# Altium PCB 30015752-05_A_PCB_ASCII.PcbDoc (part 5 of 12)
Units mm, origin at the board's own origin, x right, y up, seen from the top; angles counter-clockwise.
Board outline 100.05 x 72 mm, 10 copper layers (Top, GND_2, Signal_3, Signal_4, PWR_5, GND_6, Signal_7, Signal_8, GND_9, Bottom), stack 1.493 mm thick; 577 components, 546 nets, 2389 pads, 1412 vias.
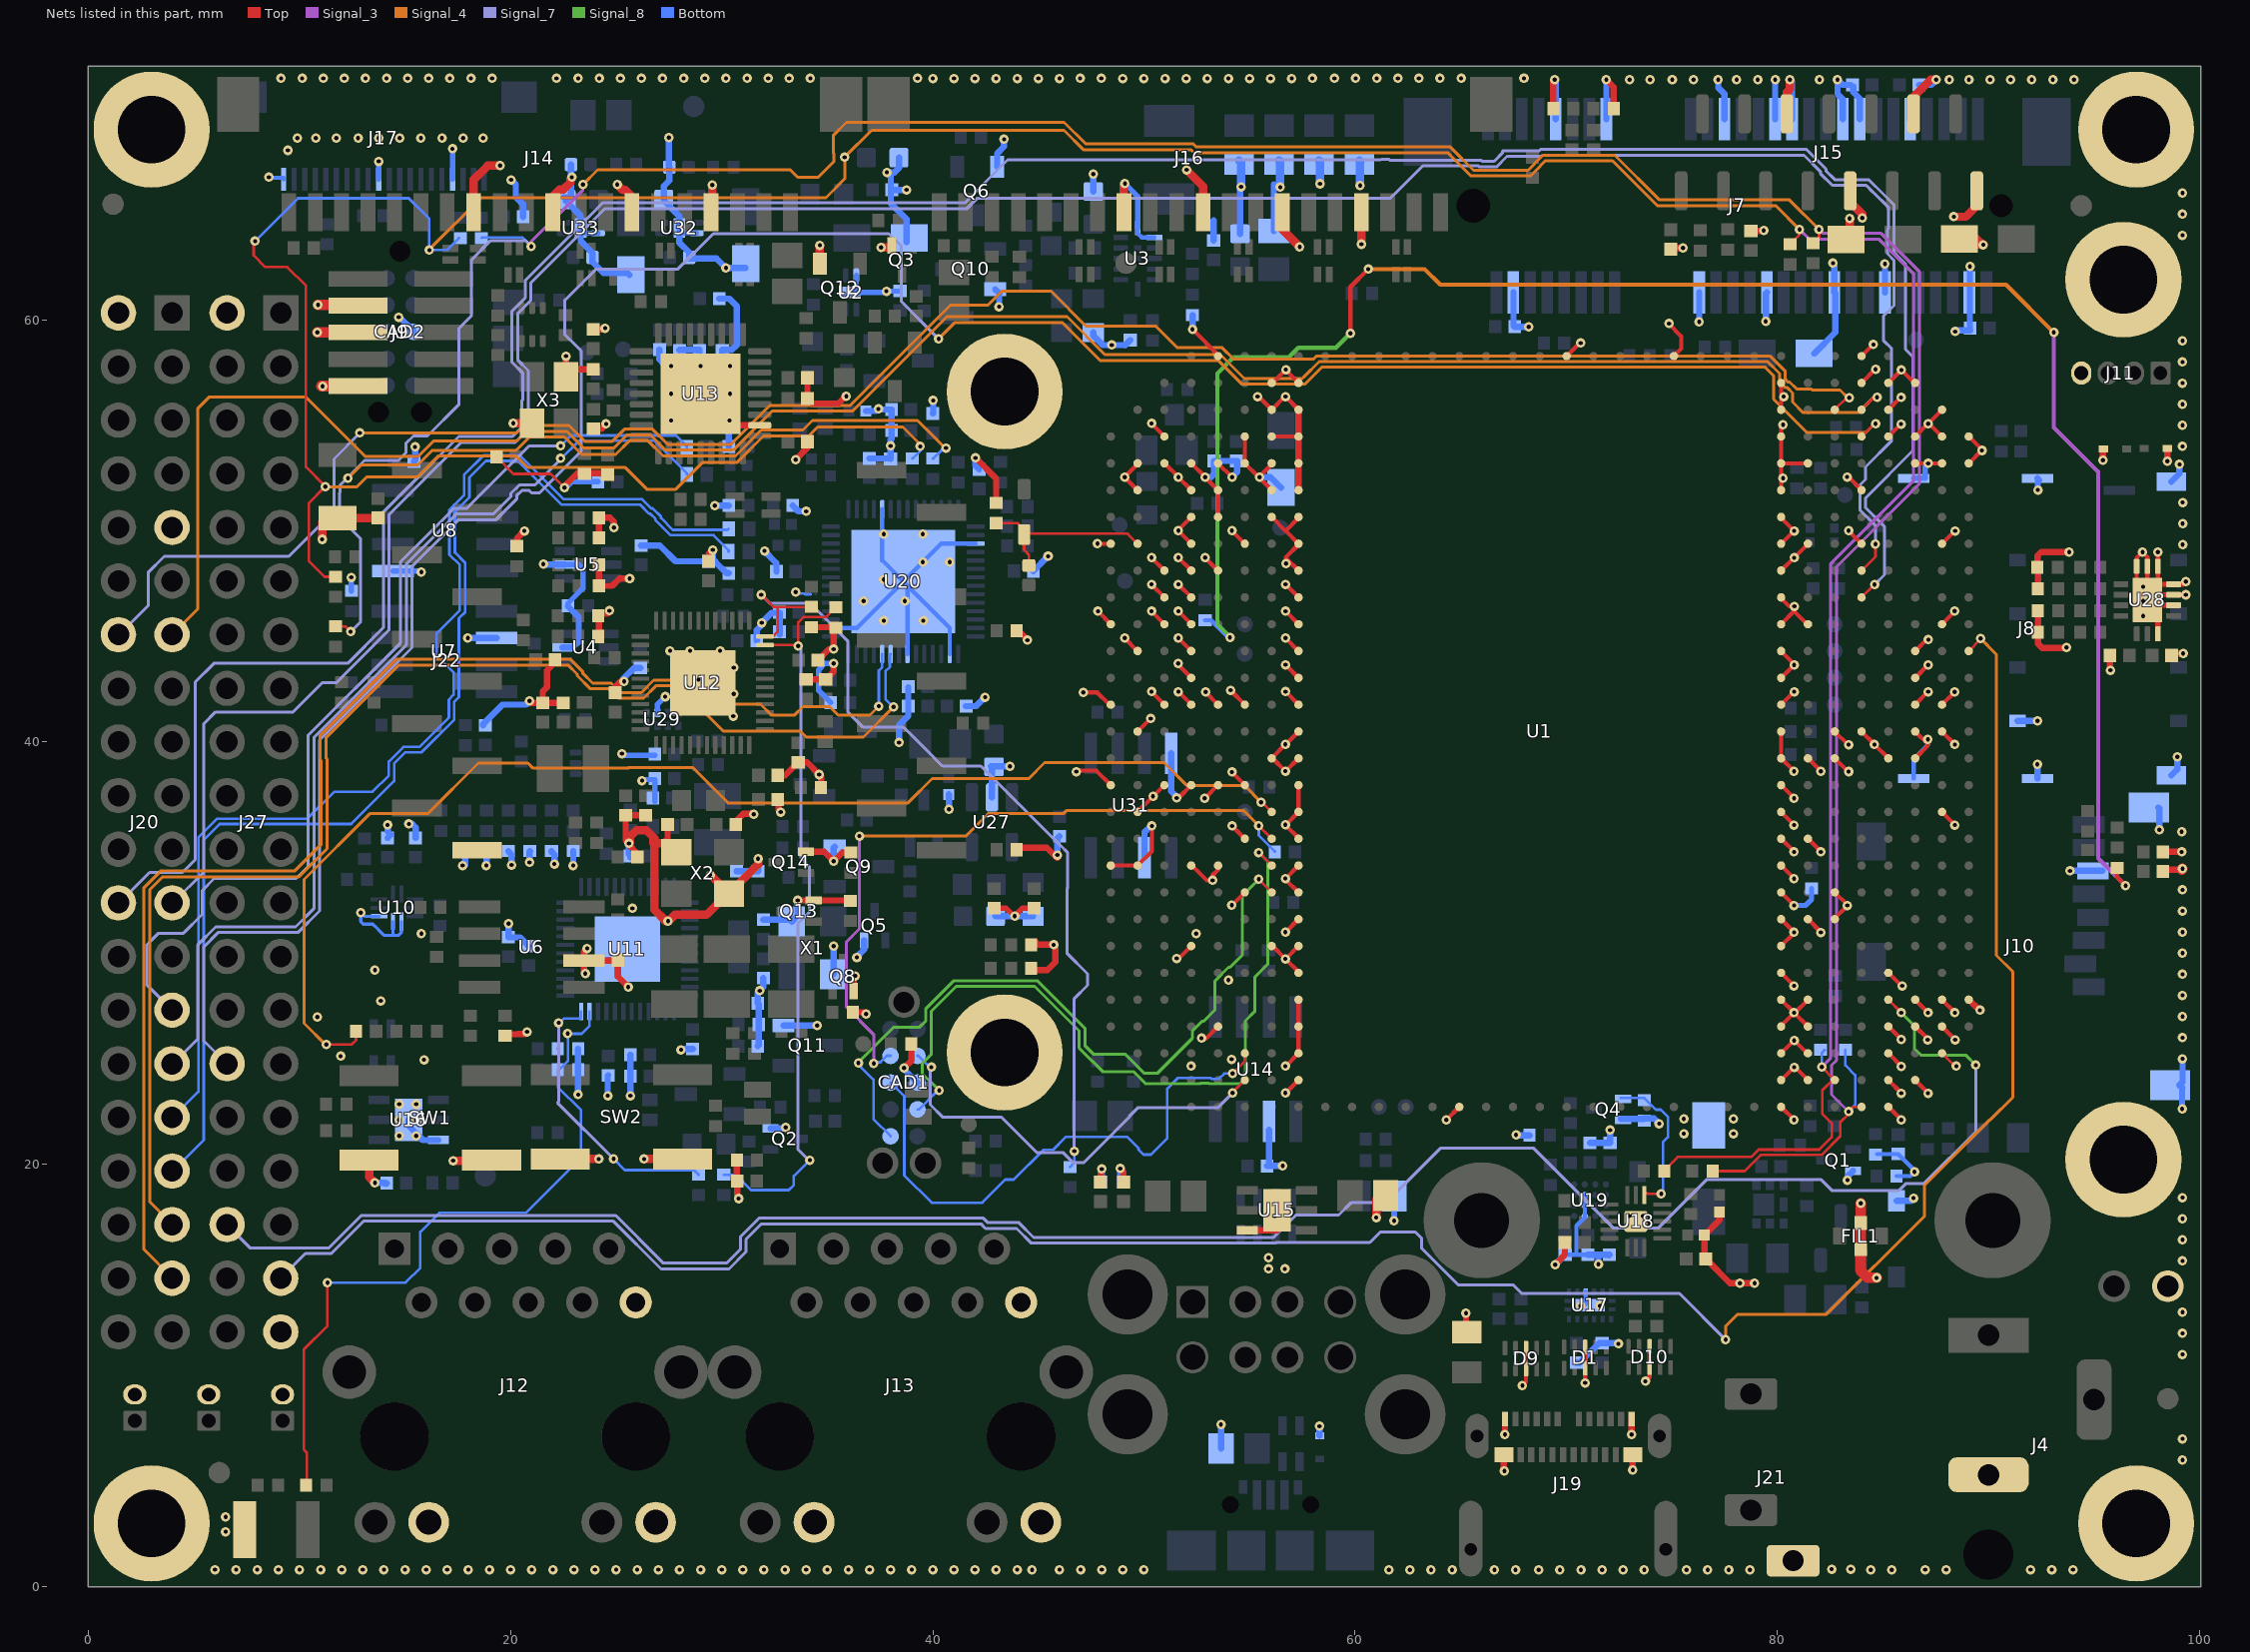
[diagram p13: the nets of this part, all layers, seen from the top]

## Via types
v1: diameter 0.45, hole 0.2, Top to Bottom, tented both sides, 1412 vias

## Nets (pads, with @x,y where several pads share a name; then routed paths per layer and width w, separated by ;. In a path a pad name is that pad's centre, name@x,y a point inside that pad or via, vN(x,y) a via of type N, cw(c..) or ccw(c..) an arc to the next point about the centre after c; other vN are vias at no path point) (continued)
GND: C1.2 C2.1 C3.1 C4.1 C5.1 C6.1 C7.2 C8.1 C9.1 C10.1 C11.1 C12.1 C15.1 C16.1 C17.1 C18.1 C19.2 C20.2 C21.2 C22.1 C23.1 C24.1 C25.1 C26.1 C27.1 C28.1 C29.2 C30.2 C31.1 C32.1 C33.1 C37.1 C38.1 C39.1 C40.1 C42.1 C43.1 C44.1 C45.1 C46.2 C47.1 C48.1 C49.1 C50.1 C51.1 C52.1 C53.1 C54.1 C55.1 C56.1 C57.1 C58.1 C59.1 C60.1 C61.1 C62.1 C63.1 C64.2 C65.1 C66.1 C67.1 C68.1 C69.1 C70.1 C71.1 C72.1 C73.1 C74.1 C75.1 C76.1 C77.1 C78.1 C80.1 C81.2 C82.2 C83.1 C84.2 C85.1 C86.1 C87.1 C88.1 C90.1 C91.1 C92.1 C93.1 C94.1 C95.1 C96.1 C97.1 C98.1 C99.1 C100.1 C101.1 C102.1 C103.1 C104.1 C105.1 C106.1 C107.1 C108.1 C109.2 C112.2 C113.2 C114.2 C115.2 C116.2 C117.2 C118.2 C119.2 C120.1 C121.2 C122.2 C123.2 C124.1 C125.2 C126.2 C128.1 C129.1 C130.2 C131.1 C132.1 C135.1 C136.1 C143.1 C145.1 C146.1 C147.1 C148.1 C149.1 C154.1 C155.2 C156.1 C157.1 C158.1 C159.2 C160.1 C161.1 CAD1.3 CAD2.3 D1.3 D1.8 D2.1 D3.A D6.1 D7.1 D9.3 D9.8 D10.3 D10.8 D14.A FIL1.2 J2.2 J3.2 J4.2 J5.2 J6.2 J7.4 J7.9 J7.15 J7.18 J7.21 J7.26 J7.27 J7.29 J7.34 J7.35 J7.37 J7.40 J7.43 J7.50 J8.5 J8.11 J8.12 J8.13 J8.14 J8.15 J8.16 J9.3 J9.5 J9.9 J10.6 J10.11 J10.12 J11.4 J12.10 J12.D2 J12.D4 J13.10 J13.D2 J13.D4 J14.4 J14.7 J14.10 J14.13 J15.6 J15.9 J15.12 J15.15 J16.4 J16.7 J16.10 J16.13 J17.1 J17.10 J17.17 J19.A1 J19.A12 J19.B1 J19.B12 J20.2 J20.9 J21.1 J22.10 J27.2 J27.39 L13.1 L14.1 L39.1 NT1.2 pad.0@43.4,25.3 pad.0@43.4,56.6 pad.0@96.4,20.225 pad.0@96.4,61.9 pad.TOOL1 pad.TOOL2 pad.TOOL3 pad.TOOL4 Q1.S Q2.S Q3.S Q4.S Q5.S Q6.S Q8.S Q9.S Q10.S Q11.S Q12.S Q13.S Q14.S R12.1 R24.1 R25.1 R27.1 R30.2 R33.1 R34.2 R37.1 R39.1 R44.1 R50.1 R59.1 R61.1 R82.1 R85.1 R87.1 R89.1 R91.1 R93.1 R95.1 R97.1 R99.1 R101.1 R108.2 R109.2 R112.1 R114.1 R117.2 R119.1 R121.1 R123.1 R125.1 R127.1 R129.1 R131.1 R133.1 R138.1 R139.1 R140.1 R141.1 R150.1 R153.1 R163.2 R189.1 R195.1 R197.2 R198.1 R214.2 R216.2 R217.1 R218.1 R258.1 SW1.1 SW1.2 SW2.1 SW2.2 U1.A4 U1.A5 U1.A25 U1.AF2 U1.AF3 U1.AF4 U1.AF5 U1.AF6 U1.AF7 U1.AF8 U1.AF9 U1.AF10 U1.AF11 U1.AF12 U1.AF13 U1.AF14 U1.AF15 U1.AF16 U1.AF17 U1.AF18 U1.AF19 U1.AF20 U1.AF21 U1.AF22 U1.AF23 U1.AF24 U1.AF25 U1.AF26 U1.AF27 U1.AF28 U1.AG2 U1.AG3 U1.AG4 U1.AG5 U1.AG6 U1.AG7 U1.AG16 U1.AG23 U1.AH4 U1.AH5 U1.AH8 U1.AH14 U1.AH17 U1.AH19 U1.AH21 U1.AJ1 U1.AJ5 U1.AJ6 U1.AJ7 U1.AJ9 U1.AJ14 U1.AJ17 U1.AJ20 U1.AJ26 U1.AK5 U1.AK6 U1.AK7 U1.AK8 U1.AK9 U1.AK10 U1.AK11 U1.AK12 U1.AK13 U1.AK14 U1.AK17 U1.AK20 U1.AK23 U1.AL4 U1.AL5 U1.AL9 U1.AL10 U1.AL11 U1.AL14 U1.AL17 U1.AM5 U1.AM6 U1.AM12 U1.AM15 U1.AM18 U1.AM20 U1.AN8 U1.AN11 U1.AN14 U1.AN17 U1.AN20 U1.B3 U1.B4 U1.B5 U1.B8 U1.B11 U1.B14 U1.B15 U1.B18 U1.B25 U1.B26 U1.B27 U1.C2 U1.C4 U1.C5 U1.C12 U1.C13 U1.C14 U1.C15 U1.C16 U1.C25 U1.C26 U1.C28 U1.D2 U1.D3 U1.D4 U1.D16 U1.D24 U1.D26 U1.D27 U1.D28 U1.D29 U1.E1 U1.E2 U1.E6 U1.E8 U1.E15 U1.F15 U1.F16 U1.F21 U1.F22 U1.G5 U1.G8 U1.G11 U1.G16 U1.G19 U1.G22 U1.G25 U1.G26 U1.G27 U1.G28 U1.H2 U1.H3 U1.H4 U1.H5 U1.H6 U1.H7 U1.H8 U1.H9 U1.H10 U1.H11 U1.H12 U1.H13 U1.H14 U1.H15 U1.H16 U1.H17 U1.H18 U1.H19 U1.H20 U1.H21 U1.H22 U1.H23 U1.H24 U1.H25 U1.H26 U1.H27 U1.H28 U1.H29 U1.M1 U1.T1 U1.Y29 U2.2 U2.5 U3.1 U3.12 U4.2 U5.2 U6.2 U7.2 U8.5 U10.1 U10.2 U10.3 U11.49 U12.49 U13.11 U13.37 U14.6 U15.3 U15.7 U16.3 U16.7 U17.11 U17.17 U18.17 U19.B3 U19.C3 U19.D3 U20.3 U20.16 U20.21 U20.30 U20.47 U20.57 U27.2 U28.2 U28.3 U28.4 U28.5 U28.6 U28.7 U28.14 U28.15 U29.2 U31.4 U31.6 U32.2 U32.5 U33.2 U33.5 X1.2 X1.4 X2.2 X2.4 X3.2 X3.4 | length 588.3
  Top w0.127: C97.1@19.34,53.5 20.14,52.7 21.9,52.7 v1(22.55,52.05) ; U1.B27@87.8,25.26 v1@88.41,24.65
  Top w0.2: v1(46.8,38.6) 46.852,38.652 47.738,38.652 U1.AN17@48.43,37.96 ; v1(47.125,42.35) 47.786,42.35 48.366,41.77 U1.AN14@48.43,41.77 ; v1(47.8,49.4) 47.81,49.39 U1.AN8@48.43,49.39 ; v1(47.82,46.2) 47.82,46.19 U1.AN11@48.43,45.58 ; U1.AN20@48.43,34.15 U1.AM20@49.7,34.15 50.38,34.83 50.377,34.833 v1(50.377,36.027) ; v1(49.09,44.93) 49.09,44.92 U1.AM12@49.7,44.31 ; U1.AM18@49.7,36.69 49.7,36.7 v1(50.427,37.427) ; U1.AM15@49.7,40.5 50.31,41.11 v1(50.32,41.11) ; U1.AM6@49.7,51.93 49.09,52.54 v1(49.09,52.55) 49.7,53.16 U1.AM5@49.7,53.2 ; v1(50.36,42.39) 50.36,42.38 U1.AL14@50.97,41.77 ; v1(50.36,46.2) 50.36,46.19 U1.AL11@50.97,45.58 ; v1(50.36,47.47) 50.36,47.46 U1.AL10@50.97,46.85 ; v1(50.36,48.74) 50.36,48.73 U1.AL9@50.97,48.12 ; v1(50.36,55.09) 50.36,55.08 U1.AL4@50.97,54.47 ; v1(50.427,37.427) 50.427,37.417 U1.AL17@50.97,37.96 ; U1.AL5@50.97,53.2 50.98,53.2 v1(51.63,52.55) 51.63,52.54 U1.AK6@52.24,51.93 ; v1(51.553,29.751) 51.651,29.751 U1.AK23@52.24,30.34 ; v1(51.553,37.352) 51.608,37.352 51.62,37.34 U1.AK17@52.24,37.96 ; v1(51.625,43.725) 51.625,43.655 U1.AK13@52.24,43.04 ; v1(51.63,42.385) 51.63,42.38 U1.AK14@52.24,41.77 ; v1(51.63,44.93) 51.63,44.92 U1.AK12@52.24,44.31 ; v1(51.63,46.2) 51.63,46.19 U1.AK11@52.24,45.58 ; v1(51.63,47.47) 51.63,47.46 U1.AK10@52.24,46.85 ; v1(51.63,48.74) 51.63,48.73 U1.AK9@52.24,48.12 ; U1.AK20@52.24,34.15 52.28,34.15 52.978,33.452 v1(53.253,33.452) 53.253,33.693 53.51,33.95 U1.AJ20@53.51,34.15 ; U1.AK8@52.24,49.39 51.63,50 v1(51.63,50.01) 51.63,50.05 U1.AK7@52.24,50.66 ; U1.AK5@52.24,53.2 52.25,53.2 v1(52.9,52.55) 52.9,52.54 U1.AJ6@53.51,51.93 U1.AJ7@53.51,50.66 ; v1(52.3,59.55) 53.51,58.34 U1.AJ1@53.51,58.28 ; v1(52.728,25.976) 52.956,25.976 U1.AJ26@53.51,26.53 ; v1(52.88,37.34) 52.89,37.34 U1.AJ17@53.51,37.96 ; v1(52.9,48.74) 52.9,48.73 U1.AJ9@53.51,48.12 ; v1(52.925,42.375) 52.925,42.355 U1.AJ14@53.51,41.77 ; U1.AJ5@53.51,53.2 54.16,52.55 v1(54.175,52.55) ; v1(54.103,42.452) 54.103,42.447 U1.AH14@54.78,41.77 ; v1(54.16,32.27) 54.17,32.27 U1.AH21@54.78,32.88 ; v1(54.17,38.58) 54.17,38.57 U1.AH17@54.78,37.96 ; v1(54.17,50.01) 54.17,50 U1.AH8@54.78,49.39 ; v1(54.178,36.027) 54.173,36.027 U1.AH19@54.78,35.42 ; U1.AH4@54.78,54.47 U1.AH5@54.78,53.2 55.43,52.55 v1(55.475,52.55) ; v1(55.38,56.36) 55.43,56.36 U1.AG3@56.05,55.74 56.67,56.36 v1(56.71,56.36) 56.71,56.35 U1.AF3@57.32,55.74 ; U1.AG23@56.05,30.34 56.09,30.34 v1(56.7,29.73) ; U1.AG7@56.05,50.66 56.7,50.01 56.71,50.01 ; U1.AG6@56.05,51.93 55.475,52.505 v1(55.475,52.55) ; U1.AG5@56.05,53.2 56.05,53.16 55.475,52.585 v1(55.475,52.55) ; U1.AG4@56.05,54.47 U1.AF4@57.32,54.47 ; U1.AG2@56.05,57.01 56.09,57.01 v1(56.72,57.64) 56.72,57.61 U1.AF2@57.32,57.01 ; v1(56.7,23.38) 56.71,23.38 U1.AF28@57.32,23.99 ; v1(56.7,24.65) 56.71,24.65 U1.AF27@57.32,25.26 U1.AF26@57.32,26.53 U1.AF25@57.32,27.8 U1.AF25@57.32,27.84 ; v1(56.7,31) 56.71,31 U1.AF22@57.32,31.61 ; v1(56.71,42.39) 56.71,42.38 U1.AF14@57.32,41.77 ; v1(56.71,43.66) 56.71,43.65 U1.AF13@57.32,43.04 ; v1(56.71,44.93) 56.71,44.92 U1.AF12@57.32,44.31 ; v1(56.71,46.2) 56.71,46.19 U1.AF11@57.32,45.58 ; v1(56.71,47.47) 56.71,47.46 U1.AF10@57.32,46.85 ; v1(56.728,48.452) 56.728,48.688 ; U1.AF24@57.32,29.07 57.32,29.11 v1(56.7,29.73) ; U1.AF23@57.32,30.34 56.71,29.73 v1(56.7,29.73) ; U1.AF21@57.32,32.88 56.7,33.5 v1(56.7,33.54) 56.71,33.54 U1.AF20@57.32,34.15 ; U1.AF19@57.32,35.42 57.32,35.46 v1(56.7,36.08) 56.71,36.08 U1.AF18@57.32,36.69 U1.AF17@57.32,37.96 ; U1.AF16@57.32,39.23 56.71,38.62 v1(56.7,38.62) 56.09,39.23 U1.AG16@56.05,39.23 56.05,39.24 v1(56.7,39.89) 56.71,39.89 U1.AF15@57.32,40.5 ; U1.AF9@57.32,48.12 56.74,48.7 56.728,48.688 ; U1.AF7@57.32,50.66 57.32,50.62 56.71,50.01 ; v1(64.32,22.11) 64.33,22.11 U1.Y29@64.94,22.72 ; v1(67.925,9.525) 68.1,9.7 D9.8@68.1,10.3 D9.3@68.1,11.3 ; U1.T1@70.02,58.28 70.64,58.9 v1(70.68,58.9) ; v1(70.9,9.65) D1.8@70.9,11.3 ; v1(73.75,9.725) 73.95,9.925 D10.3@73.95,10.375 D10.8@73.95,11.375 ; v1(74.875,59.821) 74.875,59.792 75.457,59.21 75.457,58.637 U1.M1@75.1,58.28 ; U1.H29@80.18,22.72 80.79,22.11 v1(80.79,22.1) ; U1.H28@80.18,23.99 80.79,24.6 v1(80.8,24.6) 80.84,24.6 U1.G28@81.45,23.99 ; U1.H27@80.18,25.26 80.79,25.87 v1(80.8,25.87) 81.41,25.26 U1.G27@81.45,25.26 ; U1.H26@80.18,26.53 80.18,26.57 v1(80.79,27.18) ; U1.H25@80.18,27.8 80.79,27.19 v1(80.79,27.18) ; U1.H24@80.18,29.07 80.79,28.46 v1(80.79,28.45) ; U1.H23@80.18,30.34 80.79,30.95 v1(80.79,30.99) 80.79,31 U1.H22@80.18,31.61 ; U1.H21@80.18,32.88 80.79,32.27 v1(80.79,32.26) ; U1.H20@80.18,34.15 80.79,33.54 v1(80.79,33.53) ; U1.H19@80.18,35.42 80.79,34.81 v1(80.79,34.8) ; U1.H18@80.18,36.69 80.79,36.08 v1(80.79,36.07) ; U1.H17@80.18,37.96 80.79,37.35 v1(80.79,37.34) ; U1.H15@80.18,40.5 U1.H16@80.18,39.23 80.79,38.62 v1(80.79,38.61) ; U1.H14@80.18,41.77 80.79,42.38 v1(80.8,42.38) ; U1.H13@80.18,43.04 80.79,43.65 v1(80.8,43.65) 80.8,43.69 U1.H12@80.18,44.31 ; U1.H11@80.18,45.58 v1@80.804,46.204 ; U1.H10@80.18,46.85 80.18,46.81 80.563,46.427 v1(80.804,46.427) v1@80.804,46.204 ; U1.H9@80.18,48.12 80.79,48.73 v1(80.8,48.73) 81.45,49.38 U1.G8@81.45,49.39 ; U1.H8@80.18,49.39 80.79,50 v1(80.8,50) 80.18,50.62 U1.H7@80.18,50.66 ; U1.H6@80.18,51.93 v1@80.18,52.525 ; U1.H3@80.18,55.74 80.18,56.28 80.26,56.36 v1(80.3,56.36) 80.18,56.48 U1.H2@80.18,57.01 ; v1(80.275,52.5) 80.205,52.5 v1@80.18,52.525 ; v1(80.275,55.025) 80.18,54.93 U1.H4@80.18,54.47 U1.H5@80.18,53.2 ; U1.G26@81.45,26.53 v1@80.8,27.18 ; U1.G25@81.45,27.8 80.83,27.18 v1@80.8,27.18 ; U1.G22@81.45,31.61 82.06,31 v1(82.06,30.98) ; U1.G19@81.45,35.42 82.06,34.81 v1(82.06,34.8) ; U1.G16@81.45,39.23 82.06,38.62 v1(82.06,38.61) ; U1.G11@81.45,45.57 U1.G11@81.45,45.58 81.41,45.58 80.804,46.186 v1@80.804,46.204 ; U1.G5@81.45,53.2 U1.H5@80.18,53.2 ; U1.F22@82.72,31.61 82.72,31.65 83.32,32.25 v1(83.32,32.26) 83.32,32.28 U1.F21@82.72,32.88 ; U1.F16@82.72,39.23 83.348,38.602 v1(83.379,38.602) ; U1.F15@82.72,40.5 83.343,39.877 v1(83.379,39.877) ; v1(83.304,52.553) 83.367,52.553 U1.E6@83.99,51.93 ; v1(83.38,50.01) 83.38,50 U1.E8@83.99,49.39 ; U1.E15@83.99,40.5 84.6,39.89 v1(84.6,39.88) 84.61,39.88 U1.D16@85.26,39.23 ; U1.E2@83.99,57.01 84.633,57.653 v1(84.654,57.653) ; U1.E1@83.99,58.28 84.554,58.844 v1(84.554,58.828) ; U1.D29@85.26,22.72 85.87,22.11 v1(85.87,22.1) ; U1.D28@85.26,23.99 85.87,23.38 v1(85.87,23.37) ; U1.D27@85.26,25.26 85.87,24.65 v1(85.87,24.64) ; U1.D26@85.26,26.53 85.87,25.92 v1(85.87,25.91) ; U1.D24@85.26,29.07 85.88,28.45 v1(85.916,28.45) ; U1.D4@85.26,54.47 85.85,55.06 v1(85.86,55.06) ; U1.D3@85.26,55.74 85.84,56.32 v1(85.86,56.32) ; U1.D2@85.26,57.01 85.87,57.62 v1(85.88,57.62) 86.49,57.01 U1.C2@86.53,57.01 ; U1.C28@86.53,23.99 87.14,23.38 v1(87.14,23.37) ; U1.C26@86.53,26.53 87.12,25.94 v1(87.12,25.9) ; U1.C25@86.53,27.8 87.14,27.19 v1(87.14,27.18) ; U1.C16@86.53,39.23 87.14,39.84 87.129,39.851 87.129,39.901 ; U1.C15@86.53,40.5 87.129,39.901 ; U1.C14@86.53,41.77 87.14,42.38 v1(87.15,42.38) ; U1.C13@86.53,43.04 87.14,43.65 v1(87.15,43.65) ; U1.C12@86.53,44.31 87.14,44.92 87.154,44.906 v1(87.154,44.852) ; U1.C5@86.53,53.2 v1(87.15,53.2) U1.B5@87.8,53.2 ; U1.C4@86.53,54.47 87.14,55.08 v1(87.15,55.08) ; v1(87.129,40.127) 87.129,39.901 ; 87.14,39.89 87.129,39.901 ; U1.B26@87.8,26.53 88.42,25.91 v1(88.42,25.9) ; U1.B25@87.8,27.8 88.41,27.19 v1(88.41,27.18) ; U1.B18@87.8,36.69 88.41,36.08 v1(88.41,36.07) ; U1.B15@87.8,40.5 88.41,39.89 v1(88.41,39.88) ; U1.B14@87.8,41.77 88.407,42.377 v1(88.404,42.377) ; U1.B11@87.8,45.58 88.41,46.19 88.404,46.196 v1(88.404,46.202) ; U1.B8@87.8,49.39 88.41,50 v1(88.42,50) ; U1.B4@87.8,54.47 87.19,55.08 v1(87.15,55.08) ; U1.B3@87.8,55.74 87.8,55.73 v1(87.15,55.08) ; v1@88.41,24.65 88.411,24.651 v1(88.479,24.651) ; U1.A5@89.07,53.2 89.68,53.81 v1(89.69,53.81) 89.69,53.85 U1.A4@89.07,54.47 ; U28.15@97.5,46.775 97.525,46.8 U28.6@97.525,48.325 97.525,48.775 v1(97.3,49) 97.025,48.725 U28.7@97.025,48.325 97.025,47.225 U28.15@97.525,46.725 ; U28.15@97.95,46.675 98.025,46.75 98.025,46.975 98.025,47.475 U28.5@98.025,48.325 v1(98.025,49) ; 56.71,50.01 56.71,50 U1.AF8@57.32,49.39 57.32,49.35 56.72,48.75 56.728,48.742 56.728,48.688 ; v1@80.18,52.525 U1.H5@80.18,53.2 ; v1(80.79,27.18) v1@80.8,27.18
  Top w0.25: U28.15@97.7,47.45 97.725,47.475 98.025,47.475 U28.4@98.775,47.475 99.225,47.475 v1(99.35,47.6) ; U28.15@97.725,46.95 97.75,46.975 98.025,46.975 U28.3@98.775,46.975 v1(99.35,46.975) ; U28.15@97.85,46.425 97.9,46.475 U28.2@98.775,46.475 ; U28.15@98,46.125 98.025,46.1 U28.14@98.025,45.125
  Top w0.254: C149.1@42.9,32.14 43.46,32.14 43.84,31.76 v1(43.88,31.76) 44.26,32.14 C148.1@44.8,32.14
  Top w0.3: R59.1@19.74,26.08 19.74,26.162 20.327,26.162 20.343,26.178 20.678,26.178 v1(20.775,26.275) ; R189.1@20.3,49.28 20.3,49.65 v1(20.65,50) ; v1(20.9,41.95) 20.99,41.86 C73.1@21.525,41.86 ; C32.1@22.11,43.9 22.11,43.776 21.725,43.391 21.725,42.6 21.525,42.4 C73.1@21.525,41.86 ; C72.1@22.5,41.86 C73.1@21.525,41.86 ; v1(22.55,52.05) 22.55,52.115 23.175,52.74 C90.1@24.6,52.74 ; v1(22.625,58.275) 22.619,58.269 X3.2@22.619,57.291 22.979,57.651 C81.2@23.919,57.651 ; v1(23.54,29.04) 23.47,29.11 U6.2@23.47,29.655 ; v1(23.625,30.225) 23.47,30.07 U6.2@23.47,29.655 ; C94.1@23.919,59.551 24.414,59.551 24.463,59.6 v1(24.475,59.6) ; C82.2@23.925,54.84 24.315,54.84 v1@24.525,55.05 ; R125.1@24.16,46.075 R125.1@24.185,46.075 ; R129.1@24.185,45.1 R125.1@24.185,46.075 ; R121.1@24.185,48.4 R119.1@24.185,47.4 24.81,47.4 25.15,47.74 v1(25.64,47.74) ; R127.1@24.185,49.625 R127.1@24.185,49.675 R131.1@24.185,50.625 24.7,50.625 24.895,50.43 v1(24.895,50.152) ; v1(24.68,46.22) 24.68,46.18 24.575,46.075 R125.1@24.185,46.075 ; C77.1@24.95,42.335 24.95,42.61 25.215,42.875 v1(25.375,42.875) ; v1(25.575,28.4) 25.09,28.885 C31.1@25.09,29.675 25.07,29.655 U6.2@23.47,29.655 ; C145.1@26.01,34.55 26.01,34.715 25.6,35.125 v1(25.6,35.2) 25.45,35.35 C66.1@25.45,36.54 C65.1@26.4,36.54 ; X2.4@27.44,35.185 C61.1@27.44,36.1 ; v1(29,56.5) 30.5,55 U13.11@31.8,55 ; C70.1@29.375,48.56 29.375,48.9 v1(29.575,49.1) ; C60.1@30.66,36.1 30.66,36.235 31.035,36.61 31.49,36.61 v1(31.52,36.58) ; C63.1@30.72,19.22 R34.2@30.72,20.2 ; C63.1@30.74,19.2 30.74,18.44 v1(30.8,18.38) ; C74.1@32.66,37.275 32.692,37.243 32.692,36.788 v1(32.8,36.68) ; C71.1@32.66,38.4 C71.1@32.677,38.417 ; C71.1@32.66,38.425 33.01,38.425 C76.1@33.625,39.04 34.04,39.04 v1(34.62,38.46) 34.705,38.375 R114.1@34.705,37.85 ; v1(33.502,53.378) 34.06,53.935 C92.1@34.06,54.225 ; v1(33.6,32.5) Q13.S@34.35,32.5 36.08,32.5 R109.2@36.1,32.48 ; Q14.S@33.99,34.8 34.86,34.8 v1(35.3,34.36) 35.7,34.76 R108.2@36.12,34.76 ; C68.1@34,42.96 C67.1@34.925,42.96 35.3,43.335 v1(35.3,43.725) ; C93.1@34.06,57.25 C96.1@34.06,56.275 34.312,56.023 35.523,56.023 35.878,56.378 v1(35.902,56.378) ; R133.1@34.25,45.44 35.3,45.44 v1(35.3,44.4) 35.085,44.4 C75.1@34.56,43.875 ; R216.2@36.21,27.2 36.76,27.2 v1(36.84,27.12) ; Q8.S@36.25,28.21 36.25,28.85 v1(36.325,28.925) ; v1(38.64,24.56) 38.98,24.9 R33.1@38.98,25.7 ; v1(42.02,53.46) 43,52.48 R258.1@43,51.33 ; R197.2@43.98,34.9 44.082,35.002 45.408,35.002 45.9,34.51 45.902,34.512 v1(45.902,34.652) ; R198.1@43.98,45.3 44.005,45.325 44.475,44.855 v1(44.475,44.825) ; R37.1@44.66,29.2 45.425,29.2 45.804,29.579 45.804,30.318 v1(45.721,30.401) 44.979,30.401 44.82,30.56 R39.1@44.66,30.4 ; C87.1@47.95,19.16 47.95,19.825 47.999,19.776 v1(48.002,19.776) ; v1(48.875,19.8) 49.025,19.65 C88.1@49.025,19.16 ; U15.3@54.9,16.875 U15.7@56.3,16.875 ; U1.AF6@57.32,51.93 U1.AF5@57.32,53.2 U1.AF4@57.32,54.47 U1.AF3@57.32,55.74 ; v1(65.253,12.951) 65.253,12.097 R214.2@65.3,12.05 ; J19.B12@67.05,6.24 67.05,5.5 v1(67.075,5.475) ; v1(67.1,7.2) J19.A1@67.1,7.94 ; R218.1@69.392,70 69.392,71.317 v1(69.45,71.375) ; v1(69.475,15.25) 69.94,15.715 C99.1@69.94,16.3 ; v1(71.9,71.375) 72.252,71.023 R217.1@72.252,70 ; v1(73.1,7.2) J19.A12@73.1,7.94 ; v1(73.15,5.525) J19.B1@73.15,6.24 ; C78.1@74.95,63.35 75.003,63.403 v1(75.529,63.403) ; C102.1@77.26,17.74 77.26,17.36 C101.1@76.55,16.65 76.55,15.585 C100.1@76.61,15.525 77.76,14.375 v1(78.225,14.375) v1(78.925,14.375) ; C22.1@78.7,64.21 C22.1@78.75,64.21 79.336,64.21 v1(79.354,64.228) ; U1.A25@89.07,27.8 89.57,27.3 v1(89.6,27.3) ; R117.2@92.345,46.225 R30.2@92.345,45.2 92.345,44.655 92.55,44.45 93.675,44.45 v1(93.7,44.475) ; R195.1@92.345,47.25 92.345,48.25 R112.1@92.32,48.275 92.32,48.82 92.5,49 v1(93.825,49) ; v1(95.425,53.35) 95.425,53.85 D6.1@95.45,53.875 ; C46.2@95.755,44.1 95.755,43.42 v1(95.775,43.4) ; C27.1@98.241,33.959 v1@99.154,33.959 ; C28.1@98.26,34.8 v1(99.15,34.8) ; v1(98.475,53.3) 98.475,53.8 D7.1@98.5,53.825 ; C64.2@98.675,44.1 98.775,44.2 v1(99.225,44.2)
  Top w0.4: v1(11.075,49.6) 11.075,50.45 11.225,50.6 C37.1@11.8,50.6 13.71,50.6 C38.1@13.725,50.615 ; SW1.2@13.3,20.2 13.302,20.198 13.302,19.398 v1(13.575,19.125) ; v1(17.276,20.176) 19.076,20.176 SW1.1@19.1,20.2 ; J14.13@18.25,65.1 18.25,66.633 18.917,67.3 v1(19.5,67.3) ; v1(20.125,55.1) 20.134,55.091 X3.4@21.019,55.091 ; J14.10@22,65.1 22,65.85 22.323,66.173 22.504,66.173 22.827,66.496 22.827,66.677 v1(22.9,66.75) ; SW2.2@22.35,20.25 v1(24.175,20.25) ; v1(25.051,66.403) 25.319,66.135 25.44,66.135 25.75,65.825 J14.7@25.75,65.1 ; v1@25.601,35.202 25.648,35.248 25.648,35.504 25.971,35.827 26.429,35.827 26.752,35.504 ; v1(26.325,20.25) SW2.1@28.15,20.25 ; X2.4@27.85,34.775 27.44,35.185 27.35,35.275 27.277,35.202 26.802,35.202 ; v1(29.45,33.7) 29.475,33.7 X2.2@30.35,32.825 ; J14.4@29.5,65.1 29.551,65.151 v1(29.551,66.378) ; v1(31.725,34.475) 31.725,34.2 X2.2@30.35,32.825 ; Q12.S@34.65,62.65 v1(34.65,63.525) ; v1(37.549,63.419) 37.954,63.419 Q3.S@38.05,63.515 ; J16.13@49.05,65.1 49.05,66.4 v1(49.1,66.45) ; v1(52.02,67.1) 52.8,66.32 J16.10@52.8,65.1 ; J16.7@56.55,65.1 56.55,64.275 v1(57.375,63.45) ; J16.4@60.3,65.1 60.3,63.581 v1(60.303,63.578) ; v1(61.003,17.476) 61.003,18.353 61.15,18.5 L14.1@61.85,18.5 ; J15.6@80.45,69.75 80.45,70.775 80.6,70.925 v1(80.6,71.375) ; C20.2@83.25,63.8 83.213,63.837 83.425,64.05 v1(83.425,64.8) ; J15.9@83.45,66.1 83.45,65.575 84.025,65 v1(84.025,64.825) ; J15.12@86.45,69.75 86.45,70.55 87.275,71.375 v1(87.525,71.375) ; v1(88.36,64.88) 88.93,64.88 89.45,65.4 J15.15@89.45,66.1 ; v1(89.754,63.553) 89.697,63.553 v1@89.675,63.575 ; v1@89.775,63.575 v1@89.675,63.575 ; 26.752,35.504 26.752,35.202 26.802,35.202 ; 26.752,35.504 26.802,35.454 26.802,35.202 ; 26.802,35.202 26.802,32.073 27.355,31.52 v1(27.46,31.52) 27.48,31.52 27.78,31.82 29.28,31.82 30.285,32.825 X2.2@30.35,32.825 ; v1@89.675,63.575 88.875,63.575 C21.2@88.625,63.825 89.025,64.225 v1@89.675,63.575
  Top w0.5: v1(10.85,59.4) J9.5@12.768,59.4 ; v1(10.875,60.7) 12.738,60.7 J9.3@12.768,60.67 ; v1(11.101,56.853) 11.042,56.853 11.035,56.86 J9.9@12.768,56.86 ; v1(83.95,18.15) 83.95,14.95 84.275,14.625 v1(84.7,14.625) ; v1@99.154,33.959 v1(99.195,34)
  Bottom w0.127: v1(33.5,47.1) 33.562,47.038 33.905,47.038 33.943,47 NT1.2@34.198,47
  Bottom w0.15: U10.3@13.775,31.75 13.075,31.75 v1(12.9,31.925) 12.9,31.5 13.023,31.377 13.477,31.377 13.727,31.127 13.727,31.123 14,30.85 14.425,30.85 ; U10.2@14.425,31.5 14.425,30.85 ; U10.1@14.825,31.5 14.825,30.975 14.7,30.85 14.425,30.85
  Bottom w0.2: v1(8.55,66.75) 8.55,66.766 8.591,66.725 9.25,66.725 J17.1@9.25,66.65 ; U20.30@35.17,45.4 36.4,45.4 U20.57@38.6,47.6 ; U20.47@37.6,51.03 37.6,48.6 U20.57@38.6,47.6 ; U20.21@38.8,44.17 U20.57@38.8,47.4 ; U20.16@40.8,44.17 40.8,45.4 U20.57@38.8,47.4 ; U20.3@42.03,49.4 40.4,49.4 v1(39.525,48.525) U20.57@38.6,47.6 ; U3.12@49.7,64.35 49.7,64.1 49.9,63.9 U3.1@50.5,63.9 ; C108.1@69.95,15.715 70.488,15.715 ; U19.B3@70.88,18.55 U19.C3@70.88,18.05 U19.D3@70.88,17.55 70.88,17.48 70.488,17.088 70.488,15.715 ; U17.17@70.925,13.375 U17.11@70.925,13.975 ; C107.1@71.025,15.715 70.488,15.715 ; R25.1@84.735,20.49 C132.1@85.725,20.49 86.5,19.715 v1(86.5,19.64) 86.31,19.45 R24.1@85.655,19.45 ; J8.13@86.46,38.27 86.46,39.2 87.129,39.869 v1(87.129,40.127) ; U20.57@38.6,47.6 U20.57@38.8,47.4
  Bottom w0.25: J17.10@13.75,66.65 v1(13.75,67.5) ; J17.17@17.25,66.65 v1(17.25,68.1) ; U33.5@23.325,64.35 23.575,64.1 U33.2@24.135,64.1 ; U32.5@28,64.35 28,64.1 U32.2@28.81,64.1 ; U2.5@36.125,61.29 36.375,61.54 U2.2@36.375,62.1 ; U2.5@36.35,61.29 37.74,61.29 v1(37.8,61.35) 37.81,61.36 C6.1@38.45,61.36 ; v1(49.1,66.45) 49.7,65.85 U3.12@49.7,64.35 ; v1(80.79,32.26) 81.335,32.26 81.625,32.55 R12.1@81.625,33.07 ; J8.14@86.46,52.49 86.47,52.5 87,52.5 87,53.05 v1(87.15,53.2)
  Bottom w0.254: v1(12.45,47.8) 12.459,47.791 R61.1@12.459,47.161 ; U8.5@14.43,48.105 15.723,48.105 v1(15.776,48.052) ; v1(22.55,52.05) 22.628,52.05 22.903,52.325 C91.1@24.14,52.325 ; U5.2@22.575,48.4 23.225,48.4 23.425,48.2 23.425,47.275 22.72,46.57 R163.2@22.72,46.45 ; v1(25.275,39.45) 25.354,39.371 26.84,39.371 C62.1@26.84,39.375 ; v1(26.225,38.175) 26.275,38.225 26.84,38.225 C55.1@26.84,37.2 ; U29.2@26.95,41.375 26.95,41.775 v1(27.325,42.15) ; v1(28.9,42.95) 29.01,42.84 C44.1@29.01,42.2 ; C123.2@35.165,41.875 34.6,42.44 34.6,43.425 34.9,43.725 v1(35.3,43.725)
  Bottom w0.3: v1(13.575,19.125) 14.042,19.125 14.1,19.067 C45.1@14.14,19.107 ; C39.1@14.175,35.46 14.326,35.611 14.175,35.761 v1(14.175,36.075) ; v1(14.7,60.12) 14.755,60.12 15.4,59.475 CAD2.3@15.4,59.43 ; U16.7@15.175,22.1 15.175,21.825 15.85,21.15 U16.3@16.575,21.15 ; v1(15.183,36.123) 15.327,36.123 15.5,35.95 C40.1@15.5,35.46 ; C33.1@15.419,53.281 15.476,53.337 v1(15.476,53.978) ; v1(17.726,34.152) 17.827,34.152 17.84,34.165 R99.1@17.84,34.832 ; v1(17.975,44.925) U7.2@19.329,44.926 ; C146.1@18.7,40.785 18.7,40.85 19.62,41.77 20.72,41.77 v1(20.9,41.95) ; v1(18.851,34.152) 18.856,34.152 18.865,34.16 R95.1@18.865,34.832 ; v1@19.875,31.375 v1(19.9,31.4) C51.1@19.9,30.76 19.912,30.748 20.437,30.748 C52.1@20.85,30.335 ; R89.1@19.89,34.832 20.05,34.672 v1(20.05,34.175) ; v1(20.025,66.625) 20.246,66.404 20.246,65.807 20.585,65.468 C80.1@20.585,64.875 ; v1(20.9,34.3) 20.9,34.817 R87.1@20.915,34.832 ; v1(21.55,48.425) 21.575,48.4 U5.2@22.575,48.4 ; R93.1@21.94,34.832 21.925,34.817 22.075,34.667 v1(22.075,34.225) ; U4.2@22.45,44.475 22.925,44.475 23.225,44.775 23.225,45.918 22.72,46.423 R163.2@22.72,46.45 ; C161.1@22.865,67.35 22.865,65.805 22.525,65.805 C160.1@22.63,65.7 22.63,65.62 23.325,64.925 U33.5@23.325,64.35 23.325,63.725 23.885,63.165 C158.1@23.885,62.95 23.885,62.74 24.4,62.225 25.525,62.225 C159.2@25.625,62.125 ; v1(22.965,34.15) R97.1@22.965,34.832 ; v1(23.2,23.3) R91.1@23.2,24.475 R101.1@23.2,25.475 ; v1(24.601,23.251) 24.601,24.189 24.6,24.19 C57.1@24.625,24.215 ; v1(25.375,42.875) 25.375,43.035 25.855,43.515 C29.2@26.15,43.515 ; v1(25.6,35.2) 25.6,34.685 25.7,34.585 C59.1@25.665,34.55 ; v1(25.676,23.251) 25.68,23.255 C49.1@25.68,24.167 C50.1@25.68,25.192 ; C30.2@26.175,49.31 27.065,49.31 27.815,48.56 C69.1@29.375,48.56 ; C83.1@27.05,58.59 27.05,58.125 27.275,57.9 v1@27.6,57.9 ; v1(27.5,68.625) 27.5,67.24 C157.1@27.515,67.225 27.515,66.59 27.255,66.33 C156.1@27.255,65.7 27.255,65.645 28,64.9 U32.5@28,64.35 ; R140.1@28,58.57 R139.1@28.95,58.57 28.95,57.95 v1@29,57.9 ; U32.5@28,64.1 28,63.65 28.46,63.19 C154.1@28.46,62.95 28.46,62.898 29.752,62.898 v1(30.2,62.45) C155.2@31.125,62.45 ; v1(28.075,25.425) 28.115,25.465 C58.1@28.625,25.465 ; v1(29.575,49.1) 29.575,48.76 C69.1@29.375,48.56 ; v1(29.675,51.2) C113.2@30.34,51.2 ; C95.1@29.885,61 30.356,61 30.709,60.646 30.709,58.801 30.478,58.57 R138.1@30.025,58.57 30.025,58.075 30.2,57.9 v1@30.4,57.9 ; C116.2@30.34,48 30.228,48 29.698,48.53 29.698,48.56 C69.1@29.375,48.56 ; C112.2@30.34,54 30.34,55.04 v1@30.4,55.1 ; C48.1@30.7,33.885 C47.1@31.725,33.885 v1(31.725,34.475) ; C117.2@31.66,44.8 31.66,45.3 31.9,45.54 v1(31.9,45.65) 32.375,46.125 32.74,46.125 C129.1@32.74,45.1 ; C53.1@31.71,25.6 31.755,25.645 R82.1@31.755,26.625 31.755,27.58 C56.1@31.71,27.625 31.71,28.135 v1(31.8,28.225) 31.975,28.4 C42.1@31.975,28.815 ; C43.1@31.975,31.585 33.24,31.585 X1.4@33.325,31.5 33.6,31.775 v1(33.6,32.5) ; v1(32.027,49.052) 32.027,49.048 32.59,48.485 C115.2@32.59,48.075 ; Q2.S@32.31,21.7 33,21.7 33.027,21.727 v1(33.027,21.751) ; Q11.S@32.925,26.575 v1(34.525,26.575) ; C114.2@33.36,51.2 33.635,50.925 v1(34,50.925) ; X1.2@35.275,29 35.3,29.025 v1(35.3,30.34) ; v1(35.3,34.36) 35.3,35 Q9.S@35.35,35.05 ; v1(36.402,29.801) 36.376,29.801 36.75,30.175 Q5.S@36.75,30.61 ; C109.2@36.825,55.675 37.325,55.675 v1(37.425,55.775) 37.45,55.75 C120.1@38.04,55.75 C122.2@38.04,54.75 ; C130.2@37,53.435 37.975,53.435 C131.1@38,53.41 v1(38,54.025) 38,54.32 38.04,54.36 C122.2@38.04,54.6 ; C8.1@38.395,67.675 38.395,67.195 38.178,66.978 v1(37.827,66.978) 37.827,66.973 38.01,66.79 C9.1@38.01,66.15 ; v1(38.4,39.975) 38.4,40.8 38.84,41.24 C125.2@38.84,41.7 C126.2@38.84,42.6 ; v1(38.64,24.56) 38.64,24.5 CAD1.3@39.27,23.87 ; C7.2@38.75,63.675 38.75,64.77 38.01,65.51 C9.1@38.01,66.15 ; v1(38.75,66.15) C9.1@38.06,66.15 C9.1@38.01,66.15 ; C121.2@40,55.56 40.02,55.58 v1(40.02,56.18) ; C4.1@40.75,37.52 40.76,37.51 v1(40.76,36.82) ; C124.1@41.56,41.7 C124.1@41.585,41.7 42.05,41.7 v1(42.475,42.125) ; v1(42.02,53.46) 42.02,53.09 C119.2@42.2,52.91 ; U27.2@42.8,37.38 42.8,38.8 42.75,38.85 v1(43.65,38.85) ; Q10.S@42.95,61.45 43.15,61.25 43.14,61.24 v1(43.14,60.62) ; C5.1@42.97,31.75 42.98,31.76 v1(43.88,31.76) 44.74,31.76 R27.1@44.75,31.75 ; Q6.S@43.05,67.25 43.05,67.875 43.375,68.2 v1(43.375,68.55) ; C118.2@44.76,48.1 v1(45.46,48.8) ; v1(45.902,34.652) 45.902,35.438 45.9,35.44 C147.1@46,35.54 ; R50.1@47.6,59.4 47.6,59.25 48.047,58.803 v1(48.477,58.803) 49.097,58.803 49.105,58.795 C136.1@49.35,59.04 ; C135.1@47.6,66.07 v1(47.6,66.9) ; C85.1@47.95,19.16 48.002,19.212 v1(48.002,19.776) ; v1(48.875,19.8) 48.875,19.31 C86.1@49.025,19.16 ; U31.6@50.025,34.53 50.025,35.725 50.36,36.06 50.377,36.043 v1(50.377,36.027) ; U31.4@51.295,39.47 51.295,37.675 51.6,37.37 51.582,37.352 v1(51.553,37.352) ; v1(52.3,59.55) R44.1@52.3,60.22 ; v1(52.9,52.55) 53.175,52.55 53.325,52.7 C2.1@53.325,53.315 C3.1@54.375,53.315 54.425,53.315 54.425,53.158 54.415,53.148 54.415,52.79 v1(54.175,52.55) ; C12.1@53.3,63.76 53.3,64.7 ; L39.1@53.65,6.55 v1(53.65,7.675) ; C11.1@54.55,64.07 v1@54.55,66.45 ; v1(55.475,52.55) 56,52.55 C1.2@56.5,52.05 ; C84.2@55.835,19.925 C84.2@55.925,19.925 ; U14.6@55.925,21.63 C84.2@55.925,19.925 ; C10.1@56.15,64.2 56.15,66.4 ; v1(56.575,19.925) C84.2@55.925,19.925 ; v1(58.32,7.6) 58.32,7.155 D2.1@58.325,7.15 ; v1(61.85,17.325) L13.1@61.85,18.5 ; J7.4@67.5,61.3 67.5,59.71 67.56,59.65 67.57,59.66 v1(68.22,59.66) ; v1(67.625,21.4) 67.65,21.375 R150.1@68.27,21.375 ; v1(69.45,71.375) 69.5,71.325 J7.9@69.5,69.5 ; v1(69.475,15.25) 69.475,15.225 69.49,15.21 69.49,15.255 C108.1@69.95,15.715 ; C98.1@70.475,10.615 70.64,10.615 71.56,11.535 C103.1@71.7,11.535 72.44,11.535 v1(72.475,11.5) ; C107.1@71.025,15.715 71.525,15.715 ; C104.1@71.13,21.01 C105.1@72.08,21.01 72.08,21.62 v1(72.075,21.625) ; v1(71.525,15.275) 71.525,15.715 ; J7.15@71.9,69.5 v1(71.9,71.375) ; C106.1@72.025,15.69 C106.1@72.05,15.715 71.525,15.715 ; Q4.S@72.59,22.15 73.66,22.15 73.68,22.17 74.16,22.17 v1(74.404,21.926) ; v1(76.3,59.9) J7.18@76.3,61.3 ; v1(77.2,71.375) 77.2,70.995 77.5,70.695 J7.21@77.5,69.5 ; v1(79.454,59.928) 79.454,61.254 J7.26@79.5,61.3 ; J7.27@79.9,69.5 v1(79.9,71.375) ; v1(80.6,71.375) 80.7,71.275 J7.29@80.7,69.5 ; C19.2@81.75,58.4 82.75,59.4 82.75,59.619 82.752,59.621 82.752,61.248 J7.34@82.7,61.3 82.7,62.62 v1(82.64,62.68) ; J7.35@83.1,69.5 83.1,70.45 82.85,70.7 v1(82.85,71.375) 83.1,71.125 C23.1@83.465,71.125 ; v1(83.325,19.25) 83.325,19.435 Q1.S@83.59,19.7 ; C23.1@83.6,71.05 83.6,70.775 83.9,70.475 J7.37@83.9,69.5 ; J7.40@85.1,61.3 v1(85.1,62.64) ; D3.A@85.65,18.275 86.325,18.275 v1(86.45,18.4) ; J7.43@86.3,69.5 86.3,70.437 C26.1@86.781,70.919 ; C26.1@86.71,71.125 87.275,71.125 v1(87.525,71.375) ; v1(88.42,59.44) 88.48,59.5 89.14,59.5 89.125,59.515 v1(89.125,62.525) ; J8.5@91.38,41 v1(92.325,41) ; J8.12@92.32,38.27 v1(92.32,38.94) ; J8.15@92.32,52.49 92.4,52.41 92.34,52.35 v1(92.34,51.94) ; v1(93.86,33.9) J10.6@94.95,33.9 J10.6@95.4,33.9 ; J10.11@98.05,36.9 98.1,36.85 v1(98.1,35.85) ; J8.11@98.67,38.43 98.95,38.71 v1(98.95,39.3) ; J8.16@98.67,52.33 99.05,52.71 v1(99.05,53.15) ; v1(99.175,22.625) 99.175,23.585 99.195,23.605 99.05,23.75 99.195,23.895 v1(99.195,25)
  Bottom w0.4: C18.1@54.5,67.55 54.606,67.444 v1(54.606,66.292) ; C17.1@56.4,67.55 56.453,67.497 v1(56.453,66.278) ; C16.1@58.3,67.55 58.35,67.5 58.34,67.49 v1(58.34,66.44) ; C15.1@60.2,67.55 60.25,67.5 60.24,67.49 v1(60.24,66.36)
  other v1: 44.7,0.8 61.6,0.8 62.6,0.8 63.6,0.8 64.6,0.8 66.6,0.8 67.6,0.8 68.7,0.8 69.7,0.8 70.7,0.8 71.7,0.8 72.7,0.8 73.7,0.8 75.7,0.8 76.7,0.8 77.7,0.8 78.7,0.8 84.425,0.8 85.425,0.8 6,0.805 7,0.805 8,0.805 9,0.805 10,0.805 11,0.805 12,0.805 13,0.805 14,0.805 15,0.805 16,0.805 17,0.805 18,0.805 19,0.805 20,0.805 21,0.805 22,0.805 23,0.805 24,0.805 25,0.805 26,0.805 27,0.805 28,0.805 29,0.805 30,0.805 31,0.805 32,0.805 33,0.805 34,0.805 35,0.805 36,0.805 37,0.805 38,0.805 39,0.805 40,0.805 41,0.805 42,0.805 43,0.805 44,0.805 46,0.805 47,0.805 48,0.805 49,0.805 50,0.805 82.575,0.825 83.475,0.825 87,0.805 88,0.805 92,0.805 93,0.805 94,0.805 6.5,2.6 6.5,3.3 99.195,6 99.195,7 99.195,11 99.195,12 99.195,13 70.68,13.3 71.6,13.3 55.9,15.05 56.675,15.05 99.195,15.425 55.9,15.575 99.195,16.425 99.195,17.425 56.2,17.55 72.975,17.55 73.625,17.55 99.195,18.425 14.725,21.35 15.525,21.35 75.575,21.45 77.925,21.45 14.725,22.1 15.525,22.1 75.575,22.15 77.925,22.15 14.725,22.85 15.525,22.85 52.225,24.65 15.901,24.951 54.15,24.975 11.95,25.125 99.195,26 10.85,26.975 99.195,27 13.85,27.74 99.195,28 54,28.725 99.195,29 13.575,29.2 99.195,30 15.776,30.927 52.475,30.925 99.195,31 99.195,32 25.775,32.125 99.195,33 99.15,35.75 30.55,41.225 30.575,42.275 30.575,43.525 27.55,44.325 28.5,44.325 29.925,44.325 37.675,45.75 39.55,45.75 97.325,45.975 36.725,46.675 38.675,46.675 97.325,46.675 97.325,47.35 37.675,47.7 40.8,48.525 99.2,49.35 37.675,49.85 39.525,49.85 99.2,50.35 99.2,51.35 99.195,54 99.195,55 24.525,55.07 27.6,55.225 30.375,55.225 99.195,56 27.6,56.5 30.4,56.5 99.195,57 27.6,57.81 29,57.81 30.4,57.81 99.195,58 99.195,59 99.195,64 99.195,65 99.195,66 9.45,68.025 9.9,68.6 10.775,68.6 11.75,68.6 12.775,68.6 13.75,68.6 14.75,68.6 15.75,68.6 16.75,68.6 17.75,68.6 18.7,68.6 73,71.375 73.975,71.375 75.025,71.375 76.025,71.375 78.075,71.375 79.075,71.375 82,71.375 88.15,71.375 89.075,71.375 90.075,71.375 91.05,71.375 92.05,71.375 93.05,71.375 94.05,71.375 9.125,71.435 10.125,71.435 11.125,71.435 12.125,71.435 13.125,71.435 14.125,71.435 15.125,71.435 16.125,71.435 17.125,71.435 18.125,71.435 19.125,71.435 22.175,71.435 23.2,71.435 24.2,71.435 25.2,71.435 26.2,71.435 27.2,71.435 28.2,71.435 29.2,71.435 30.2,71.435 31.2,71.435 32.2,71.435 33.2,71.435 34.2,71.435 39.275,71.435 40,71.43 41,71.43 42,71.43 43,71.43 44,71.43 45,71.43 46,71.43 46.975,71.435 47.975,71.435 49,71.43 50,71.43 51,71.43 52,71.43 53,71.43 54,71.43 55,71.43 56,71.43 57,71.43 57.975,71.435 59.025,71.435 60.025,71.435 61.025,71.435 62.025,71.435 63.025,71.435 64.025,71.435 65.025,71.435 68,71.435
GPIO0_12: J27.36 U1.D25 | length 101.3
  Top w0.127: U1.D25@85.26,27.8 85.87,27.19 v1(85.87,27.18)
  Signal_8 w0.142: v1(85.87,27.18) 86.5,26.55 86.5,25.473 86.8,25.173 88.927,25.173 v1(89.4,24.7)
  Signal_7 w0.142: J27.36@6.56,17.14 7.65,16.05 11.4,16.05 12.925,17.575 24.988,17.575 26.05,16.513 26.05,16.506 27.237,15.319 30.231,15.319 30.881,15.969 30.881,16.559 31.25,16.929 31.25,16.931 31.77,17.451 42.392,17.451 42.609,17.234 44.079,17.234 44.775,16.538 56.138,16.538 57.2,17.6 59.225,17.6 59.81,18.185 61.465,18.185 64.042,20.762 68.463,20.762 72.25,16.975 74.35,16.975 76.644,19.269 82.081,19.269 82.6,18.75 85.75,18.75 86.1,19.1 86.95,19.1 89.4,21.55 v1(89.4,24.7)
GPIO4_19: J27.30 U1.E4 | length 120.2
  Top w0.127: U1.E4@83.99,54.47 84.6,55.08 84.602,55.078 v1(84.654,55.078)
  Signal_4 w0.142: v1@40.225,59.1 v1(40.275,59.1) 41.05,59.875 46.125,59.875 47.925,58.075 53.515,58.075 54.643,56.948 57.614,56.948 57.849,57.182 58.418,57.751 79.424,57.751 79.825,57.35 79.825,56.237 81.412,54.65 84.18,54.65 84.608,55.078 v1(84.654,55.078)
  Signal_7 w0.142: J27.30@6.56,24.76 5.462,25.858 5.462,30.295 6.142,30.975 9.925,30.975 10.95,32 10.95,40.094 15.329,44.473 15.329,48.308 17.553,50.532 19.309,50.532 20.284,51.507 20.284,51.664 20.532,51.912 20.882,51.912 20.996,51.798 21.372,51.798 23.35,53.777 23.35,58.525 22.577,59.298 22.577,60.925 24.053,62.402 27.928,62.402 29.607,64.08 37.92,64.08 38.508,63.492 38.508,60.867 v1(40.275,59.1)
GPIO4_20: J20.13 U1.E3 | length 100.5
  Top w0.127: U1.E3@83.99,55.74 84.58,56.33 84.585,56.325 v1(84.725,56.325)
  Signal_4 w0.142: J20.13@3.965,45.085 5.193,46.313 5.193,55.806 5.736,56.35 10.289,56.35 13.114,53.525 15.622,53.525 15.899,53.802 15.899,53.805 16.353,54.259 20.3,54.259 20.758,54.717 22.662,54.717 23.454,53.925 24.896,53.925 25.521,54.55 26.606,54.55 27.331,53.825 30.543,53.825 32.398,55.68 36.207,55.68 40.671,60.144 46.356,60.144 48.15,58.35 53.621,58.35 54.754,57.217 57.503,57.217 57.58,57.294 58.306,58.02 79.535,58.02 80.108,57.448 80.108,57.063 80.388,56.783 80.475,56.783 80.723,56.535 80.723,56.1 81.223,55.6 83.84,55.6 84.565,56.325 v1(84.725,56.325)
  Signal_7 w0.142: J20.13@3.98,45.1 J20.13@4,45.08
GPIO4_21: J20.14 U1.F3 | length 95.7
  Top w0.127: U1.F3@82.72,55.74 83.3,56.32 83.317,56.303 v1(83.404,56.303)
  Signal_4 w0.142: v1(12.86,54.64) 20.3,54.64 20.647,54.987 22.773,54.987 23.535,54.225 24.8,54.225 25.394,54.819 26.717,54.819 27.437,54.1 30.437,54.1 32.287,55.949 36.095,55.949 40.846,60.7 42.621,60.7 43.273,61.352 45.598,61.352 47.25,59.7 50.562,59.7 51.587,58.675 53.704,58.675 54.231,58.148 58.044,58.148 58.186,58.29 79.647,58.29 80.377,57.56 80.377,57.175 80.499,57.052 80.587,57.052 80.913,56.726 81.604,56.726 81.659,56.671 82.969,56.671 83.337,56.303 v1(83.404,56.303)
  Signal_7 w0.142: J20.14@1.46,45.08 2.831,46.451 2.831,48.028 3.6,48.797 9.497,48.797 11.633,50.934 11.633,51.91 11.648,51.925 11.648,52.275 11.633,52.29 11.633,53.413 v1(12.86,54.64)
GPIO5_09: J27.37 U1.A12 | length 117.5
  Top w0.127: U1.A12@89.07,44.31 89.625,44.865 v1(89.625,44.9)
  Signal_4 w0.142: v1(77.55,11.7) 77.55,12.325 78.125,12.9 82.325,12.9 86.975,17.55 86.975,19.021 90.058,22.104 90.079,22.104 91.15,23.175 91.15,29.125 90.375,29.9 90.375,44.15 v1(89.625,44.9)
  Signal_7 w0.142: J27.37@9.1,14.6 10.281,15.781 11.512,15.781 13.037,17.306 24.869,17.306 27.125,15.05 30.342,15.05 31.15,15.858 31.15,16.448 31.519,16.817 31.519,16.819 31.881,17.181 42.281,17.181 42.497,16.965 43.967,16.965 44.663,16.269 56.25,16.269 56.281,16.3 60.7,16.3 61.2,16.8 62.85,16.8 63.15,16.5 63.15,16.031 ; 63.14,16.04 63.15,16.031 ; v1(77.55,11.7) 75.362,13.888 67.888,13.888 67.476,14.299 64.882,14.299 63.15,16.031
GPS_COEX: J20.23 U1.E9 | length 127.7
  Top w0.127: U1.E9@83.99,48.12 84.65,48.78 v1(84.65,49.375)
  Signal_7 w0.142: J20.23@4,32.38 5.472,33.852 5.472,40.872 6.025,41.425 9.696,41.425 11.081,42.809 11.75,42.809 14.242,45.302 14.242,50.775 17.667,54.2 20.221,54.2 20.842,54.822 20.842,57.594 20.333,58.104 20.333,60.291 20.968,60.927 20.968,61.755 24.478,65.265 41.621,65.265 42.119,65.764 61.689,65.764 63.215,67.29 65.85,67.29 65.902,67.238 66.698,67.238 67.2,67.74 68.841,67.74 68.893,67.792 81.271,67.792 82.042,67.021 82.042,66.93 82.606,66.367 84.213,66.367 84.523,66.056 84.535,66.056 85.256,65.335 85.256,64.315 85.213,64.273 85.213,63.125 85.523,62.815 85.523,60.667 85.023,60.167 85.023,59.025 85.417,58.631 85.417,54.265 84.177,53.025 84.177,52.441 83.918,52.182 83.918,50.983 84.65,50.251 v1(84.65,49.375)
I2C3_SCL: R171.1 R173.1 R175.1 R177.1 R185.1 R187.1 U1.F28 | length 193.8
  Top w0.127: v1(7.9,63.725) 7.834,63.659 7.834,63.05 8.384,62.5 9.425,62.5 10.304,61.621 10.304,53.021 v1(11.225,52.1) 10.438,51.313 10.438,48.587 11.195,47.83 R187.1@11.7,47.83 ; R173.1@74.64,19.68 74.64,19.715 75.275,20.35 78.763,20.35 79.113,20.7 81.988,20.7 82.575,21.287 82.575,21.95 82.125,22.4 82.125,23.5 U1.F28@82.668,24.042 ; R177.1@80.6,63.58 81.05,64.03 v1(81.05,64.275) ; v1(82.11,24.61) 82.11,24.6 U1.F28@82.668,24.042 ; U1.F28@82.72,23.99 U1.F28@82.668,24.042
  Signal_3 w0.142: v1(81.05,64.275) 81.503,63.822 84.806,63.822 86.456,62.172 86.456,52.375 82.533,48.452 82.533,25.033 v1(82.11,24.61)
  Signal_4 w0.142: v1(11.225,52.1) 11.248,52.077 12.702,52.077 13.175,52.55 15.575,52.55 16.565,53.54 20.265,53.54 20.794,53.012 25.413,53.012 26.45,51.975 27.825,51.975 29.086,53.236 30.716,53.236 31.98,54.5 34.125,54.5 34.55,54.925 38.575,54.925 39.402,54.098 v1(39.402,54.003) ; v1(16.15,63.3) 16.15,63.325 18.608,65.783 34.933,65.783 35.825,66.675 v1(35.825,67.7) 37.1,68.975 46.213,68.975 47.129,68.059 52.224,68.059 52.372,67.912 64.394,67.912 65.498,66.808 68.311,66.808 68.757,67.253 68.757,67.275 69.005,67.523 72.198,67.523 74.313,65.408 79.917,65.408 v1(81.05,64.275)
  Bottom w0.127: v1(7.9,63.725) 9.925,65.75 15.175,65.75 16.15,64.775 v1(16.15,63.3) 16.98,63.3 R185.1@17.55,63.87 ; R175.1@39.025,53.43 39.05,53.43 v1@39.413,53.793 ; v1(82.11,24.61) 82.11,25.28 R171.1@82.25,25.42
I2C3_SDA: R172.1 R174.1 R176.1 R178.1 R186.1 R188.1 U1.E29 | length 188.4
  Top w0.127: R188.1@11.7,45.48 12.17,45.48 v1(12.425,45.225) ; R174.1@76.94,19.68 78.452,19.68 79.218,20.446 82.093,20.446 82.985,21.338 82.985,21.997 83.375,22.388 v1(83.375,22.5) 83.595,22.72 U1.E29@83.99,22.72 ; R178.1@81.7,63.63 81.975,63.905 v1(81.975,64.275)
  Signal_3 w0.142: v1(20.975,63.475) 20.975,63.7 23.425,66.15 v1(23.425,66.4) ; v1(81.975,64.275) 82.159,64.091 84.917,64.091 86.725,62.283 86.725,52.225 82.802,48.302 82.802,24.922 82.575,24.694 82.575,23.3 v1(83.375,22.5)
  Signal_4 w0.142: v1(12.3,52.5) 12.925,53.125 15.602,53.125 16.168,53.691 16.168,53.693 16.285,53.81 20.26,53.81 20.898,54.448 22.55,54.448 23.373,53.625 24.977,53.625 25.625,54.273 26.502,54.273 27.225,53.55 30.649,53.55 31.876,54.777 33.852,54.777 34.3,55.225 39.275,55.225 40.575,53.925 v1(40.625,53.925) ; v1(23.425,66.4) 24.125,67.1 33.25,67.1 33.6,66.75 34.573,66.75 35.323,67.5 35.323,67.85 35.298,67.875 35.298,68.748 35.9,69.35 46.218,69.35 47.24,68.328 52.336,68.328 52.483,68.181 64.506,68.181 65.61,67.077 68.199,67.077 68.488,67.365 68.488,67.387 68.893,67.792 72.309,67.792 74.425,65.677 80.573,65.677 v1(81.975,64.275)
  Signal_7 w0.142: v1(12.425,45.225) 12.898,45.698 12.898,49.625 11.902,50.621 11.902,51.798 11.917,51.813 11.917,52.167 13.085,53.335 14.685,53.335 15.048,53.698 15.048,54.154 15.395,54.5 16.064,54.5 17.562,55.998 17.562,59.61 18.152,60.2 18.152,62.846 19.056,63.75 20.7,63.75 v1(20.975,63.475)
  Bottom w0.127: R186.1@18.624,63.87 18.654,63.9 20.55,63.9 v1(20.975,63.475) ; R176.1@40,53.43 40.025,53.43 v1@40.458,53.863 ; R172.1@83.225,25.42 83.225,24.691 83.691,24.225 83.691,22.816 v1(83.375,22.5)
ILIM_5V_VBUS: Q4.G R153.2 U18.6 | length 7.2
  Top w0.127: U18.6@73.7,18.55 73.8,18.65 73.85,18.6 v1(74.5,18.6)
  Bottom w0.127: Q4.G@72.59,23.15 73.66,23.15 73.68,23.13 73.705,23.13 74.242,22.593 74.475,22.593 74.819,22.248 74.819,21.289 74.585,21.054 74.585,18.685 v1(74.5,18.6)
IMX8_ON_OFF: R213.2 U1.AG18 | length 60.9
  Top w0.127: v1(11.276,25.676) 12.476,25.676 12.675,25.875 R213.2@12.675,26.3 ; v1(55.55,37.15) 55.59,37.15 U1.AG18@56.05,36.69
  Signal_4 w0.142: v1(11.276,25.676) 11.253,25.653 11.247,25.653 10.221,26.679 10.221,33.49 13.358,36.627 16.102,36.627 18.475,39 20.823,39 21.066,38.758 25.562,38.758 25.602,38.798 28.625,38.798 30.303,37.12 38.82,37.12 39.975,38.275 44.55,38.275 45.298,39.023 50.952,39.023 52.025,37.95 54.75,37.95 v1(55.55,37.15)
JTAG_TCK: CAD1.4 U1.AG20 | length 35.7
  Top w0.127: v1(55.44,34.77) 55.44,34.76 U1.AG20@56.05,34.15
  Signal_8 w0.142: v1(40.3,23.5) 39.504,24.296 39.504,24.776 39.925,25.198 39.925,27.25 41.109,28.434 44.825,28.434 46.931,26.329 46.931,25.513 48.067,24.377 49.523,24.377 50.079,23.821 52.674,23.821 52.702,23.849 53.053,23.849 53.081,23.821 54.546,23.821 54.8,24.075 54.8,26.8 55.26,27.26 55.26,28.88 55.863,29.483 55.863,34.347 v1(55.44,34.77)
  Bottom w0.127: CAD1.4@39.27,22.6 39.335,22.6 40.235,23.5 v1(40.3,23.5)
JTAG_TDI: CAD1.8 U1.AH27 | length 26.6
  Top w0.127: v1(54.2,24.3) 54.78,24.88 U1.AH27@54.78,25.26
  Bottom w0.127: CAD1.8@38,23.87 38.65,23.22 38.65,19.475 39.941,18.185 42.337,18.185 43.428,19.276 43.826,19.276 45.235,20.685 45.685,20.685 46.295,21.295 49.215,21.295 49.737,20.772 49.737,20.704 49.98,20.461 50.325,20.461 51.106,21.242 51.106,23.581 51.621,24.096 53.155,24.096 53.201,24.049 53.56,24.049 53.81,24.3 v1(54.2,24.3)
JTAG_TDO: CAD1.6 U1.AG21 | length 34.7
  Top w0.127: v1(55.44,33.5) 55.44,33.49 U1.AG21@56.05,32.88
  Signal_8 w0.142: v1(36.477,24.801) 36.477,24.827 38.15,26.5 39.375,26.5 39.656,26.781 39.656,27.362 40.998,28.703 44.937,28.703 47.2,26.44 47.2,25.625 47.6,25.225 49.102,25.225 50,24.327 50.652,24.327 52.289,25.964 52.289,26.314 52.752,26.777 52.825,26.777 53.367,27.319 53.367,28.693 54.002,29.327 54.075,29.327 54.66,29.912 54.66,32.72 v1(55.44,33.5)
  Bottom w0.127: v1(36.477,24.801) 36.477,24.773 36.452,24.748 37.193,24.007 37.193,22.137 CAD1.6@38,21.33
JTAG_TMS: CAD1.2 U1.AH28 | length 20.4
  Top w0.127: v1(54.2,23.38) 54.2,23.41 U1.AH28@54.78,23.99
  Signal_7 w0.142: v1(39.927,24.601) 39.877,24.551 39.877,22.823 40.454,22.246 43.235,22.246 44.937,20.544 46.187,20.544 46.277,20.454 46.277,20.45 46.632,20.094 47.163,20.094 49.327,22.258 49.327,22.3 49.702,22.675 53.495,22.675 v1(54.2,23.38)
  Bottom w0.127: CAD1.2@39.27,25.14 39.303,25.14 v1@39.893,24.55
JTAG_TRST_GPIO: CAD1.9 R51.1 U1.AG19 | length 34.7
  Top w0.127: v1(55.44,36.04) 55.44,36.03 U1.AG19@56.05,35.42
  Signal_3 w0.142: v1(36.525,35.55) 36.525,31.15 35.902,30.527 35.902,27.448 37.2,26.15 v1(37.2,24.775)
  Signal_4 w0.142: v1(36.525,35.55) 41.575,35.55 42.65,36.625 46.204,36.625 46.329,36.75 54.73,36.75 v1(55.44,36.04)
  Bottom w0.127: v1(37.2,24.775) 37.262,24.837 37.518,24.837 37.821,25.14 CAD1.9@38,25.14 ; v1(55.44,36.04) 55.44,35.58 56.195,34.825 R51.1@56.195,34.8
LDO3: R56.2 R221.1 | length 87.1
  Top w0.2: v1(59.78,59.36) 59.78,61.555 v1(60.625,62.4) ; R56.2@96.1,34.04 96.1,33.6 v1(96.5,33.2)
  Signal_3 w0.2: v1(93.1,59.4) 93.1,54.9 95.2,52.8 95.2,34.5 v1(96.5,33.2)
  Signal_8 w0.2: v1(54.075,44.95) 54.075,44.982 53.475,45.582 53.475,57.45 54.25,58.225 56.875,58.225 57.318,58.668 59.088,58.668 v1(59.78,59.36)
  Signal_4 w0.2: v1(60.625,62.4) 63.3,62.4 64.039,61.661 90.839,61.661 v1(93.1,59.4)
  Bottom w0.2: R221.1@52.9,45.77 53.18,45.77 54,44.95 v1(54.075,44.95)
LED_1_1000: R83.2 R100.1 R101.2 U11.24 | length 14.6
  Signal_7 w0.142: v1@22.275,26.65 v1@22.276,26.651 ; v1(22.276,26.701) v1@22.276,26.651 ; v1(24.88,20.26) 22.225,22.915 22.276,22.966 v1@22.276,26.651
  Bottom w0.127: R101.2@22.24,25.475 22.225,25.49 22.276,25.541 v1@22.276,26.665 ; v1(22.276,26.701) v1@22.276,26.665 ; U11.24@23.34,27.242 23.34,26.947 23.303,26.911 22.552,26.911 22.292,26.65 v1@22.276,26.665 ; v1(24.88,20.26) 25.414,19.726 28.679,19.726 R83.2@28.9,19.505
LED_1_ACT: R84.2 R90.1 R91.2 U11.23 | length 34
  Top w0.127: R84.2@10.32,4.8 10.35,4.83 10.35,6.35 10.2,6.5 10.2,11.225 11.325,12.35 v1(11.325,14.4)
  Bottom w0.127: v1(11.325,14.4) 15.025,14.4 15.725,15.1 15.725,16.8 16.625,17.7 20.725,17.7 23.341,20.316 23.341,22.559 22.24,23.66 R91.2@22.24,24.475 22.3,24.475 22.715,24.89 v1@22.715,26.187 ; v1(22.701,26.201) v1@22.715,26.187 ; U11.23@23.74,27.242 23.74,26.565 23.362,26.187 v1@22.716,26.187
LED_2_1000: R115.2 R132.1 R133.2 U12.24 | length 41.7
  Top w0.127: v1(31.875,46.975) 32.45,46.4 32.65,46.4 ; U12.24@32.05,45 32.425,45 32.65,45.225 32.65,46.4 ; R133.2@34.25,46.4 32.65,46.4
  Signal_7 w0.142: v1(31.875,46.975) 32.275,46.575 34.186,46.575 35.968,44.793 35.968,41.432 36.7,40.7 38.625,40.7 40.46,38.865 42.275,38.865 46.065,35.075 46.077,35.075 46.375,34.777 46.375,33.076 46.352,33.053 46.352,30 47.325,29.027 47.325,28.475 46.7,27.85 v1(46.7,20.625)
  Bottom w0.127: R115.2@46.5,19.88 46.7,20.08 v1(46.7,20.625)
LED_2_ACT: R116.2 R122.1 R123.2 U12.23 | length 35.1
  Top w0.127: U12.23@32.05,44.6 33.575,44.6 v1(33.625,44.55) 33.625,45.679 33.861,45.916 33.866,45.916 33.875,45.925 34.95,45.925 R123.2@35.4,46.375
  Signal_7 w0.142: v1(33.625,44.55) 33.751,44.424 33.751,34.501 34.154,34.098 34.154,31.95 33.6,31.396 33.6,20.725 34.125,20.2 v1(34.174,20.2)
  Bottom w0.127: R116.2@30.1,19.505 30.671,19.505 31.392,18.784 33.172,18.784 33.416,19.028 33.416,19.442 v1(34.174,20.2)
LICELL: C162.1 D13.A R258.2 U1.AM8 | length 8.8
  Top w0.127: R258.2@43,50.37 44.005,50.37 44.325,50.05 D13.A@44.325,49.87 ; C162.1@44.55,48.36 44.55,48.875 44.325,49.1 D13.A@44.325,49.83 D13.A@44.325,49.87 ; U1.AM8@49.7,49.39 49.22,49.87 D13.A@44.325,49.87
LINE1_IN_L: J20.29 L19.1 | length 47
  Signal_7 w0.142: J20.29@4,24.76 5.193,25.953 5.193,30.406 6.031,31.244 9.813,31.244 10.681,32.112 10.681,40.206 15.06,44.585 15.06,48.42 17.442,50.802 19.197,50.802 20.015,51.619 20.015,51.775 20.42,52.181 21.156,52.181 22.375,53.4 v1(22.375,53.435)
  Bottom w0.127: v1(22.375,53.435) 22.41,53.435 23.24,54.265 26.82,54.265 28.345,52.74 L19.1@28.345,52.675
LINE1_IN_R: J20.27 L18.1 | length 46
  Signal_7 w0.142: J20.27@3.965,27.305 2.775,28.495 2.775,30.4 3.325,30.95 4.504,30.95 5.394,31.841 5.394,32.963 5.966,33.535 9.835,33.535 10.412,34.112 10.412,40.317 14.79,44.696 14.79,48.531 17.33,51.071 17.921,51.071 20.875,54.025 v1(22.375,54.025) ; J20.27@3.98,27.32 J20.27@4,27.3
  Bottom w0.127: v1(22.375,54.025) 22.869,54.519 27.841,54.519 28.345,54.015 L18.1@28.345,53.95
LINE2_IN_L: J20.33 L21.1 | length 57.6
  Bottom w0.127: J20.33@4,19.68 5.468,21.148 5.468,35.37 6.213,36.115 12.453,36.115 14.487,38.149 14.487,38.975 15.028,39.516 15.79,39.516 17.332,41.057 17.332,41.907 17.554,42.129 17.554,45.853 17.846,46.145 17.846,48.491 17.359,48.978 17.359,50.893 18.05,51.583 18.05,52.537 18.828,53.316 20.336,53.316 22.405,51.246 26.125,51.246 26.556,50.816 26.622,50.816 26.866,50.572 26.866,50.506 27.576,49.796 29.615,49.796 30.32,49.09 L21.1@30.32,49.025
LINE2_IN_R: J20.31 L20.1 | length 55.6
  Bottom w0.127: J20.31@4,22.22 5.214,23.434 5.214,35.476 6.108,36.369 10.373,36.369 11.655,37.651 13.47,37.651 14.233,38.415 14.233,39.08 14.923,39.77 15.685,39.77 17.078,41.162 17.078,42.012 17.3,42.234 17.3,43.3 16.5,44.1 16.5,45.158 17.592,46.25 17.592,48.386 17.105,48.873 17.105,50.998 17.796,51.688 17.796,52.642 18.723,53.57 20.441,53.57 22.51,51.5 26.231,51.5 26.661,51.07 26.727,51.07 27.12,50.677 27.12,50.611 27.681,50.05 30.27,50.05 L20.1@30.32,50.1
LINE_OUT_L: J20.37 U20.24 | length 66.1
  Signal_4 w0.142: J20.37@4,14.6 2.633,15.967 2.633,33.108 3.414,33.889 9.764,33.889 11.033,35.158 11.033,39.091 10.983,39.14 10.983,40.312 14.588,43.917 22.833,43.917 23.427,43.323 23.427,43.25 23.89,42.787 24.768,42.787 25.21,42.344 26.19,42.344 26.775,42.929 28.043,42.929 29.173,41.8 31.839,41.8 32.375,41.264 33.439,41.264 33.85,41.675 35.117,41.675 35.517,41.275 37.015,41.275 v1(37.44,41.7)
  Bottom w0.127: v1(37.44,41.7) 37.44,43.39 37.599,43.549 37.599,44.169 U20.24@37.6,44.17
LINE_OUT_R: J20.35 U20.23 | length 64.4
  Signal_4 w0.142: J20.35@4,17.14 2.902,18.238 2.902,32.996 3.525,33.619 9.969,33.619 11.302,34.952 11.302,39.202 11.252,39.252 11.252,40.201 14.7,43.648 22.721,43.648 23.158,43.212 23.158,43.138 23.778,42.517 24.656,42.517 25.099,42.075 26.302,42.075 26.887,42.66 27.932,42.66 30.069,40.523 33.717,40.523 33.754,40.486 33.754,40.477 34.001,40.229 36.709,40.229 v1(38.14,41.66)
  Bottom w0.127: U20.23@38,44.17 37.964,44.133 37.964,43.555 37.76,43.351 37.76,42.041 v1(38.14,41.66)
LTE_PRI: J20.24 U1.E10 | length 133.4
  Top w0.127: U1.E10@83.99,46.85 84.6,47.46 v1(84.61,47.46)
  Signal_7 w0.142: J20.24@1.46,32.38 2.902,33.822 4.455,33.822 5.066,34.434 5.066,42.841 5.95,43.725 12.285,43.725 13.973,45.413 13.973,50.886 17.556,54.469 20.093,54.469 20.548,54.925 20.548,55.275 20.521,55.302 20.521,56.148 20.573,56.2 20.573,57.483 20.063,57.992 20.063,60.402 20.699,61.038 20.699,61.867 24.367,65.534 41.509,65.534 43.546,67.571 61.222,67.571 61.253,67.601 61.603,67.601 61.645,67.56 65.961,67.56 66.013,67.508 66.587,67.508 66.992,67.913 66.992,67.987 67.015,68.01 68.73,68.01 68.782,68.062 81.383,68.062 82.312,67.133 82.312,67.042 82.717,66.636 84.324,66.636 84.635,66.325 84.646,66.325 85.525,65.446 85.525,63.194 86.075,62.644 86.075,58.6 86.425,58.25 86.425,53.807 84.187,51.568 84.187,51.095 85.073,50.208 85.073,47.923 v1(84.61,47.46)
